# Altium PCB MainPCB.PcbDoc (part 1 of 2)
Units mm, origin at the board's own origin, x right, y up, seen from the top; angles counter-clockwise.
Board outline 105.16 x 70.61 mm, 2 copper layers (Top Layer, Bottom Layer); 130 components, 114 nets, 556 pads, 141 vias.
Unrouted connection lines stored in the file: 1.
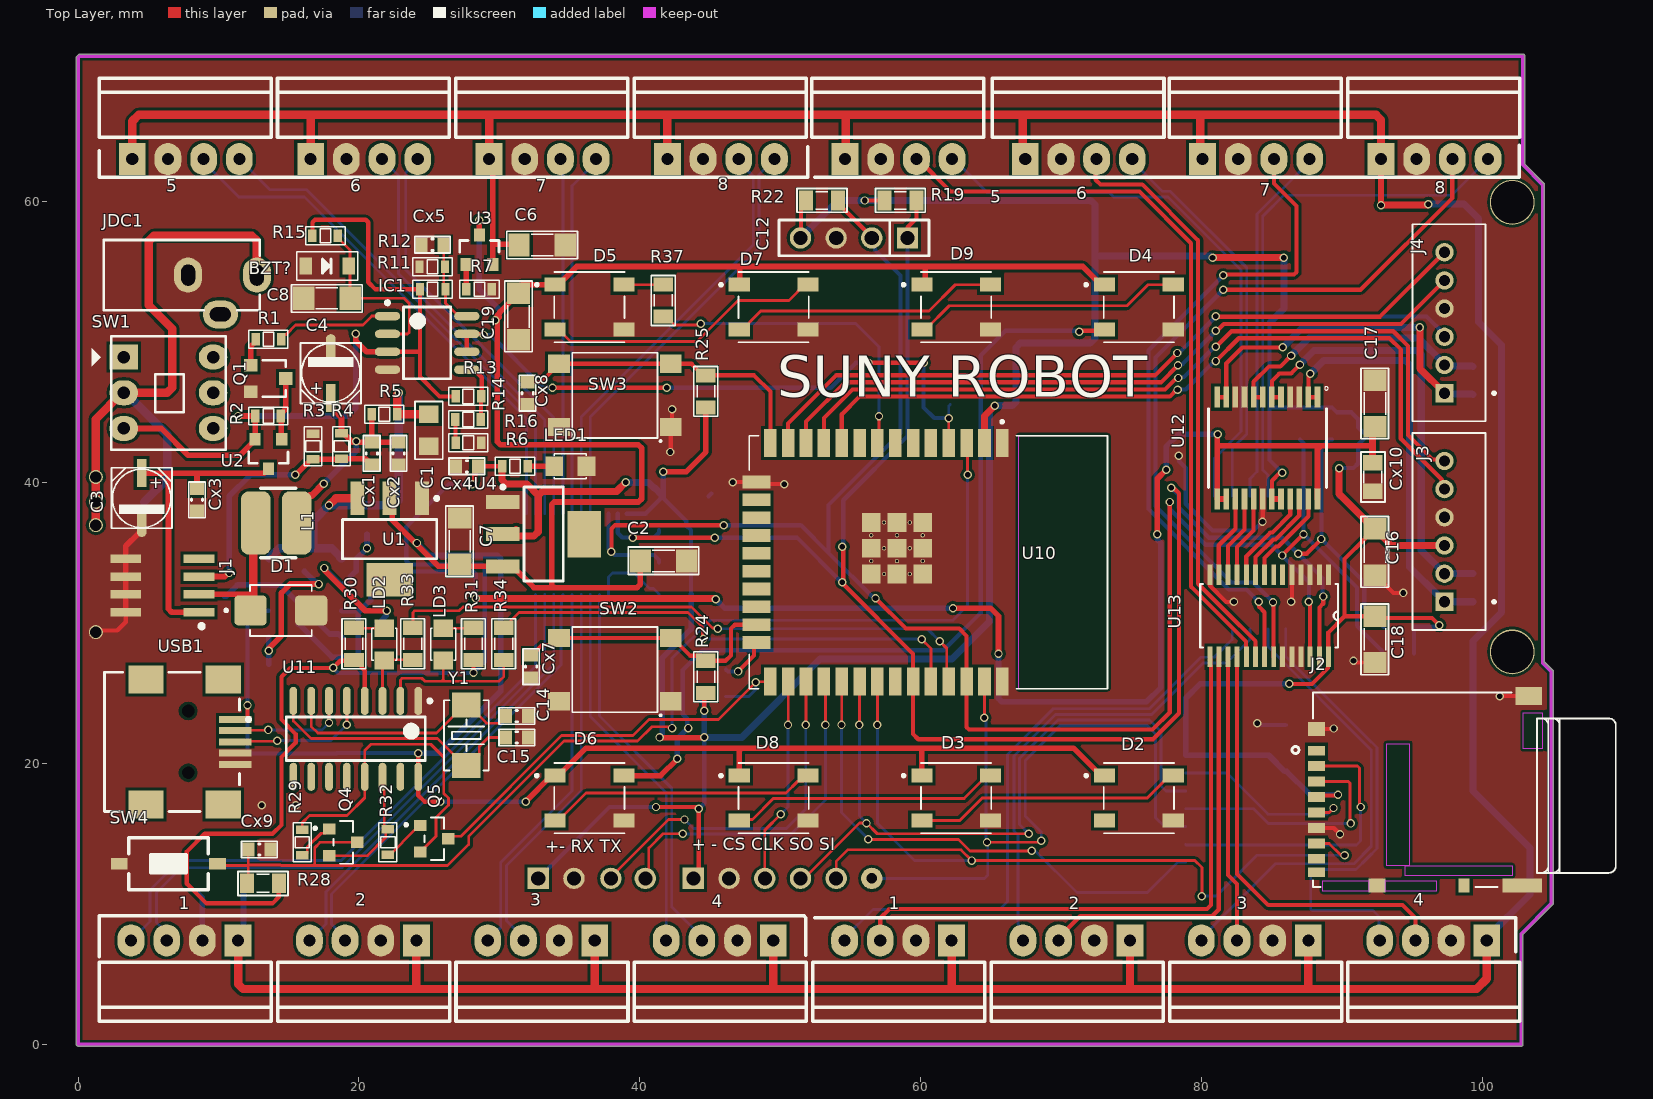
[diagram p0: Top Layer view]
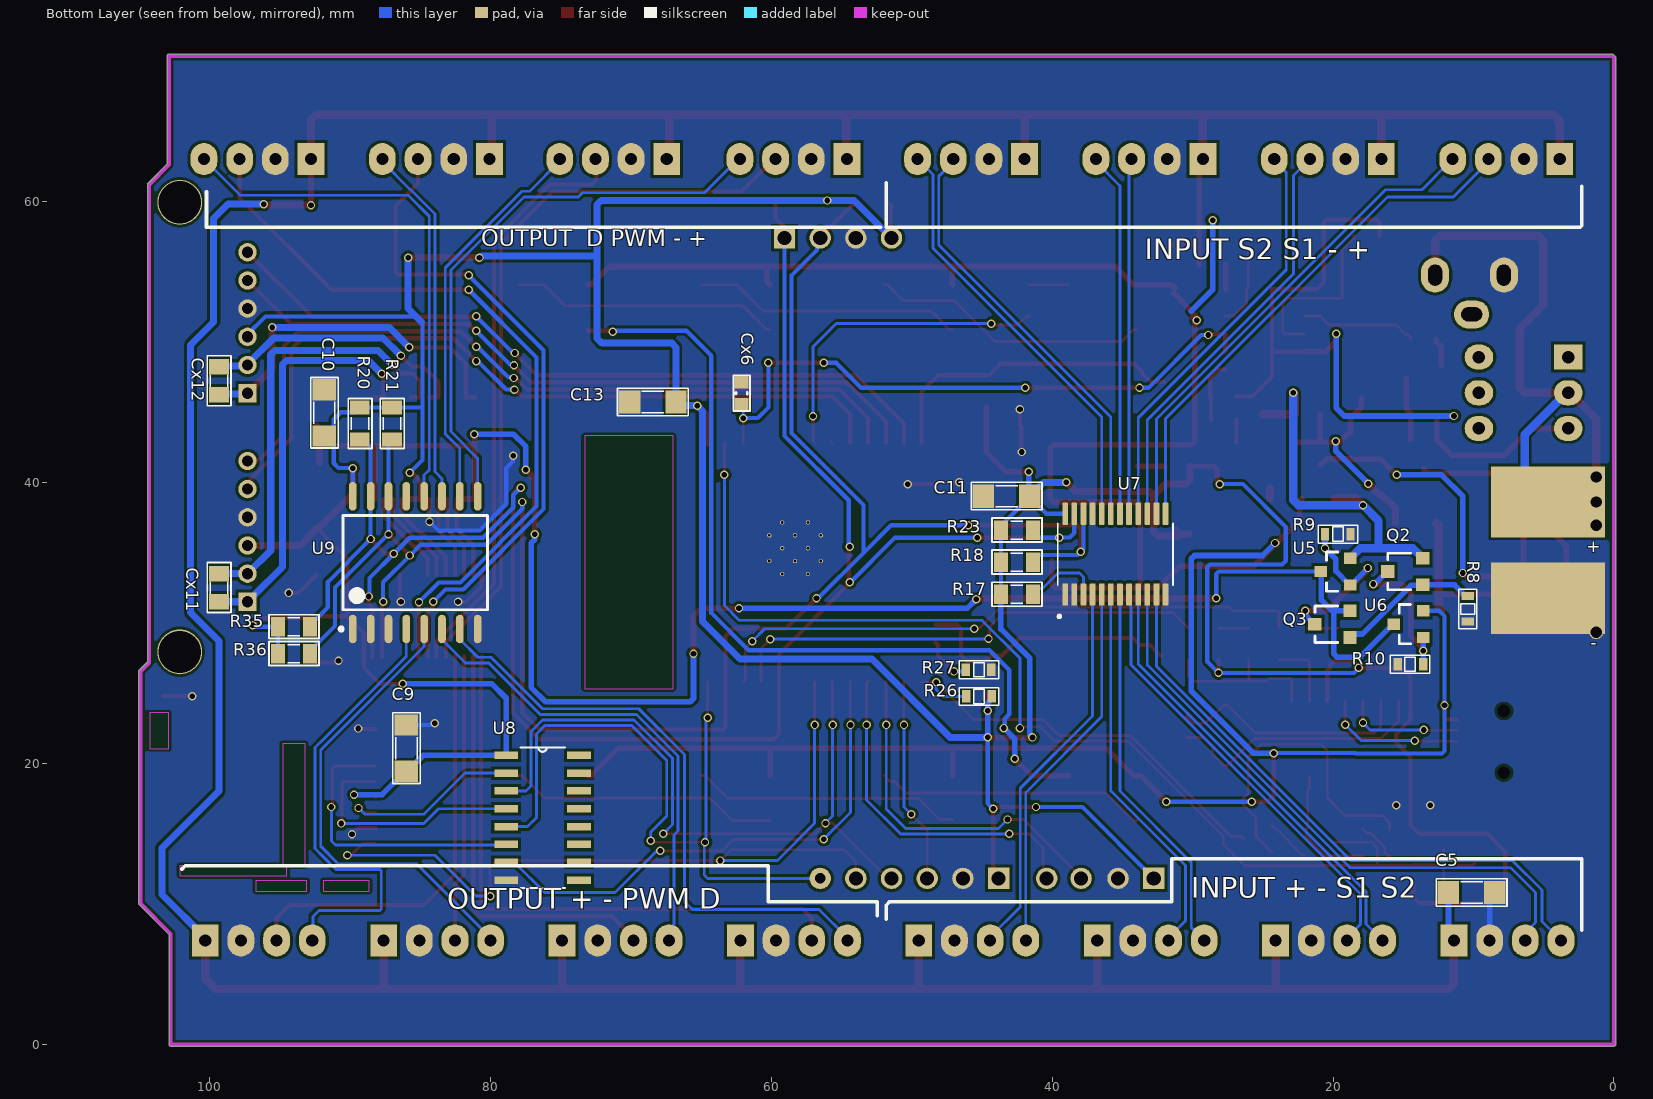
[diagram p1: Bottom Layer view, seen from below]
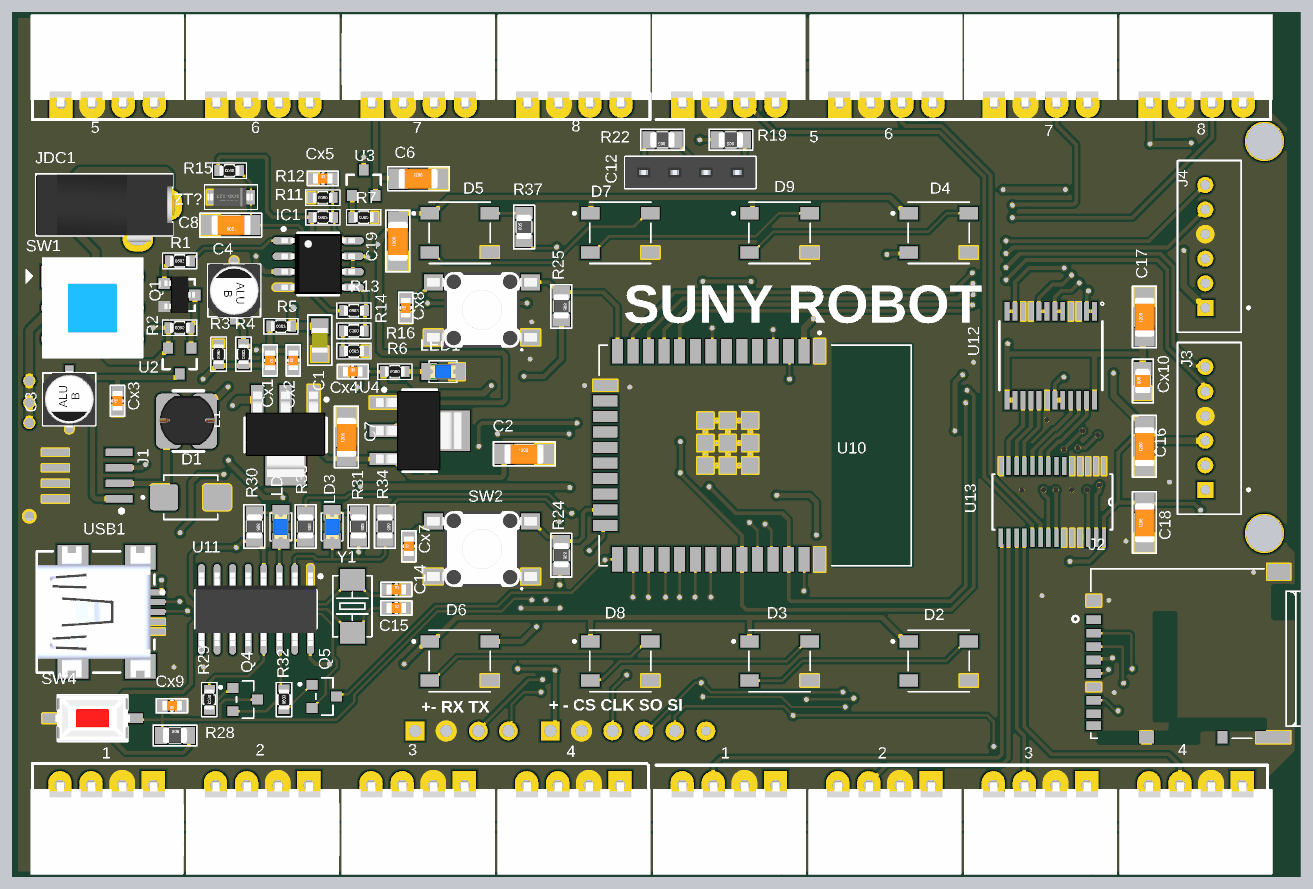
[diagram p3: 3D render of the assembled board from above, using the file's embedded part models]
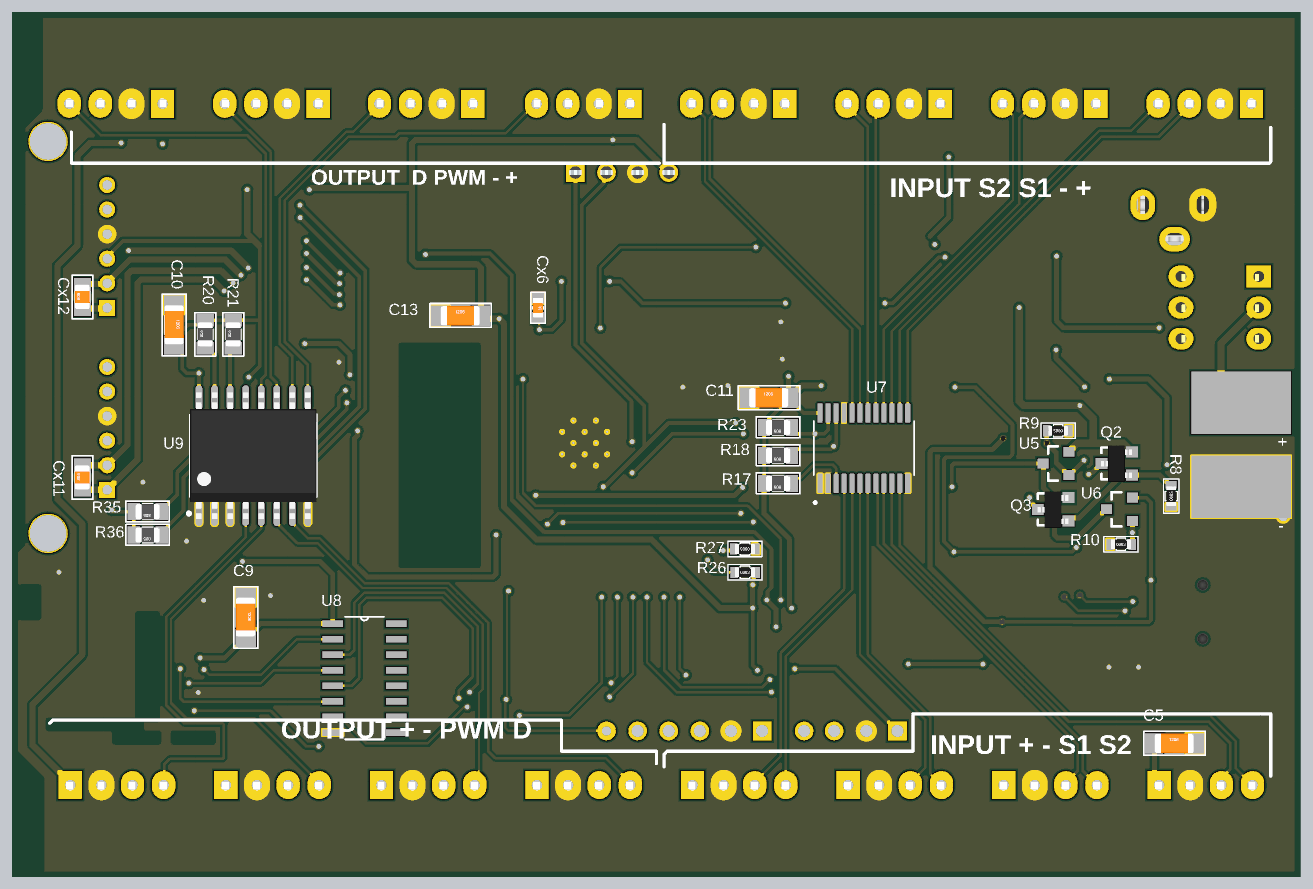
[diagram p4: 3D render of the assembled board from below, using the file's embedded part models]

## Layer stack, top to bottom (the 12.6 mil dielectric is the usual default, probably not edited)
Top Solder: solder mask 0.0102, Solder Resist, Dk 3.5
Top Layer: signal copper 0.0356
Dielectric 1: dielectric 0.32, FR-4, Dk 4.8
Bottom Layer: signal copper 0.0356
Bottom Solder: solder mask 0.0102, Solder Resist, Dk 3.5

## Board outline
0,-0.127 cw(c0,0) -0.127,0 -0.127,70.231 cw(c0,70.231) -0.09,70.322 -0.09,70.321 0.037,70.448 0.036,70.448 cw(c0.127,70.358) 0.127,70.485 102.87,70.485 cw(c102.87,70.358) 102.997,70.358 102.997,62.664 104.357,61.304 104.357,61.305 cw(c104.267,61.214) 104.394,61.214 104.394,27.231 104.992,26.633 104.992,26.634 cw(c104.902,26.543) 105.029,26.543 105.029,10.033 cw(c104.902,10.033) 104.992,9.942 104.992,9.943 102.87,7.821 102.87,0.127 cw(c102.743,0.127) 102.853,0.064 cw(c102.743,0) 102.87,0 cw(c102.743,0) 102.743,-0.127

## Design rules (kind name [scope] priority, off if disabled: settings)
Clearance [All] p1: gap=0.2 ignorepadtopadclearanceinfootprint=FALSE
PlaneClearance [All] p1: clearance=0.5
PlaneConnect [All] p1: planeconnectstyle=Relief reliefexpansion=0.5 reliefentries=4 reliefconductorwidth=0.5 reliefairgap=0.5
PolygonConnect [All] p1: connectstyle=Direct reliefconductorwidth=0.254 reliefentries=4 polygonreliefangle="90 Angle" airgapwidth=0.254
RoutingVias [All] p1: holewidth=0.4 width=0.6 viastyle="Through Hole" minholewidth=0.4 minwidth=0.6 maxholewidth=0.4 maxwidth=0.6
SolderMaskExpansion [All] p1: expansion=0.102 istentingtop=FALSE
Width Width_4 [InNetClass('Motor')] p1: maxlimit=0.5 minlimit=0.3 preferedwidth=0.4
Width Width_3 [InNetClass('LED')] p2: maxlimit=0.4 minlimit=0.2 preferedwidth=0.3
Width Width_2 [InNetClass('MCU')] p3: maxlimit=0.4 minlimit=0.2 preferedwidth=0.3
Width Width_1 [InNetClass('S_Power')] p4: maxlimit=0.4 minlimit=0.2 preferedwidth=0.3
Width [InNetClass('POWER')] p5: maxlimit=0.6 minlimit=0.4 preferedwidth=0.5
28 further rules are at their usual default settings.

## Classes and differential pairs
net class S_Power: +12 ADC_POWER EN_POWER_BAT GND NetBZT?_2 NetCx5_2 NetIC1_5 NetR14_2
net class POWER: +5 +5L +9 +12 +Vin +VM EN_POWER_BAT GND NetC3_1 NetC4_1 NetCx1_2 NetD1_C NetLED1_1 NetQ1_2 NetQ1_3 NetR7_2 TP TP1 TP2 VCC
net class Motor: +VM AO1 AO2 BO1 BO2 DIR_MA1 DIR_MA2 DIR_MB1 DIR_MB2 GND HAL_CHA_M1 HAL_CHA_M2 HAL_CHB_M1 HAL_CHB_M2 NetLabel438 NetLabel439 PWM_A PWM_B S1 S2 S3 S4 S5 S6 S7 S8 SCL SDA VCC
net class MCU: +5 ADC_POWER BT_Config BT_IN C_LED_WS2812 D+ D- DTR_CH340 EN GND GPIO_0 GPIO_2 HAL_CHA_M1 HAL_CHA_M2 HAL_CHB_M1 HAL_CHB_M2 MCU_RX MCU_TX NetLED2_1 NetLED3_1 NetQ4_1 NetQ5_1 NetR17_1 OP1 OP2 OP3 OP4 OP5 OP6 OP7 OP8 RST_CH340 S1 S2 S3 S4 S5 S6 S7 S8 SCL SCL_0 SCL_1 SCL_2 SCL_3 SCL_4 SCL_5 SCL_6 SCL_7 SD_CLK SD_CS SD_MOSI SDA SDA_0 SDA_1 SDA_2 SDA_3 SDA_4 SDA_5 SDA_6 SDA_7 SPI_CLK SPI_CS SPI_CS_SREEN SPI_MISO SPI_MOSI U2_RX U2_TX USB_RX USB_TX VCC XI XO
net class LED: +5 C_LED_WS2812 GND NetD5_4 OUT_1 OUT_2 OUT_3 OUT_4 OUT_5 OUT_6 OUT_7
component class Motor: C16 C17 C18 Cx10 Cx12 J3 J4 R35 U12 U13
component class MCU: 1 2 3 4 5 6 7 8 C9 C10 C11 C12 C13 C14 C15 Cx7 Cx8 Cx9 J2 LD2 LD3 Q4 Q5 R17 R18 R19 R20 R21 R22 R23 R24 R25 R26 R27 R28 R29 R31 R33 SW2 SW3 SW4 U7 U8 U9 U10 U11 USB1 Y1
component class LED: C19 D2 D3 D4 D5 D6 D7 D8 D9 R37
component class Power: + - BZT? C1 C2 C3 C4 C5 C6 C7 C8 Cx1 Cx2 Cx3 Cx4 Cx5 Cx6 D1 IC1 J1 JDC1 L1 LED1 Q1 Q2 Q3 R1 R2 R3 R4 R5 R6 R7 R8 R9 R10 R11 R12 R13 R14 R15 R16 SW1 U1 U2 U3 U4 U5 U6

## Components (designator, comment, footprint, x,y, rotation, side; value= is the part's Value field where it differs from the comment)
1 "Header 4" Header_4_ngang 62.193,7.392 r180 top locked (schematic designator P11)
1 "Header 4" Header_4_ngang 11.393,7.392 r180 top locked (schematic designator P1)
2 "Header 4" Header_4_ngang 74.893,7.392 r180 top locked (schematic designator P9)
2 "Header 4" Header_4_ngang 24.093,7.392 r180 top locked (schematic designator P2)
3 "Header 4" Header_4_ngang 87.593,7.392 r180 top locked (schematic designator P15)
3 "Header 4" Header_4_ngang 36.793,7.392 r180 top locked (schematic designator P3)
4 "Header 4" Header_4_ngang 100.293,7.392 r180 top locked (schematic designator P16)
4 "Header 4" Header_4_ngang 49.493,7.392 r180 top locked (schematic designator P4)
5 "Header 4" Header_4_ngang 54.61,63.018 r0 top (schematic designator P12)
5 "Header 4" Header_4_ngang 3.864,63.018 r0 top locked (schematic designator P5)
6 "Header 4" Header_4_ngang 67.437,63.018 r0 top (schematic designator P10)
6 "Header 4" Header_4_ngang 16.564,63.018 r0 top locked (schematic designator P6)
7 "Header 4" Header_4_ngang 80.064,63.018 r0 top (schematic designator P13)
7 "Header 4" Header_4_ngang 29.264,63.018 r0 top locked (schematic designator P7)
8 "Header 4" Header_4_ngang 92.764,63.018 r0 top (schematic designator P14)
8 "Header 4" Header_4_ngang 41.964,63.018 r0 top (schematic designator P8)
+ "Ac" BAT_BK-6223 4.699,38.608 r180 top (schematic designator BT1)
- "Pos" BAT_BK-6223 4.699,31.75 r180 top (schematic designator BT2)
BZT? "Diode SMD" DIO-SMD-123 17.743,55.398 r180 top value=1N5007
C1 "104" C-0805 24.982,43.714 r90 top value=103
C2 "22uF 16V" CN-SMD-1206 41.656,34.417 r0 top value=103
C3 "47uF/16V" CAP-ALU-SMD-5.5x5.5 4.535,38.888 r270 top
C4 "47uF/16V" CAP-ALU-SMD-5.5x5.5 17.997,47.778 r90 top
C5 "22uF 16V" CN-SMD-1206 10.16,10.795 r180 bottom value=103
C6 "22uF 16V" CN-SMD-1206 33.02,56.896 r0 top value=103
C7 "22uF 16V" CN-SMD-1206 27.178,35.789 r90 top value=103
C8 "10uF 16V" CN-SMD-1206 17.743,53.112 r180 top value=103
C9 "22uF 6.3" CN-SMD-1206 85.979,21.107 r270 bottom value=103
C10 "22uF 6.3" CN-SMD-1206 91.821,44.983 r270 bottom value=103
C11 "22uF 6.3" CN-SMD-1206 43.27,39.015 r180 bottom value=103
C12 "Header4" JP4-C1T 59.055,57.404 r180 top
C13 "22uF 6.3V" CN-SMD-1206 68.453,45.72 r180 bottom value=103
C14 "22pF" CN-SMD-0603 31.242,23.368 r0 top value=103
C15 "22pF" CN-SMD-0603 31.242,21.844 r0 top value=103
C16 "22uF 6.3V" CN-SMD-1206 92.329,35.027 r90 top value=103
C17 "22uF 16V" CN-SMD-1206 92.329,45.593 r90 top value=103
C18 "22uF 6.3V" CN-SMD-1206 92.329,28.804 r90 top value=103
C19 "22uF 6.3" CN-SMD-1206 31.369,51.791 r90 top value=103
Cx1 "2.2nF" CN-SMD-0603 20.918,42.063 r270 top value=33pF
Cx2 "104" CN-SMD-0603 22.823,42.063 r90 top value=33pF
Cx3 "104" CN-SMD-0603 8.472,38.761 r90 top value=33pF
Cx4 "104" CN-SMD-0603 27.686,41.148 r0 top value=33pF
Cx5 "100nF" CN-SMD-0603 25.236,56.922 r0 top value=33pF
Cx6 "104" CN-SMD-0603 62.103,46.355 r270 bottom value=33pF
Cx7 "104" CN-SMD-0603 32.258,26.886 r90 top value=33pF
Cx8 "104" CN-SMD-0603 32.004,46.355 r90 top value=33pF
Cx9 "104" CN-SMD-0603 12.917,13.869 r180 top value=33pF
Cx10 "104" CN-SMD-0805 92.177,40.386 r90 top value=33pF
Cx11 "104" CN-SMD-0805 99.314,32.512 r90 bottom value=33pF
Cx12 "104" CN-SMD-0805 99.314,47.244 r90 bottom value=33pF
D1 "SS34" DIOM5336X265N 14.441,30.887 r0 top
D2 "WS2812 5050" LED_1655 75.524,17.526 r0 top
D3 "WS2812 5050" LED_1655 62.524,17.526 r0 top
D4 "WS2812 5050" LED_1655 75.524,52.476 r0 top
D5 "WS2812 5050" LED_1655 36.412,52.476 r0 top
D6 "WS2812 5050" LED_1655 36.412,17.526 r0 top
D7 "WS2812 5050" LED_1655 49.524,52.476 r0 top
D8 "WS2812 5050" LED_1655 49.524,17.526 r0 top
D9 "WS2812 5050" LED_1655 62.524,52.476 r0 top
IC1 "LM358" SO8 24.855,49.937 r0 top
J1 "XL1509_5V" SO08 5.999,32.665 r90 top
J2 "DM3AT-SF-PEJM5" HRS_DM3AT-SF-PEJM5 88.179,17.703 r90 top
J3 "1735446-6" TE_1735446-6 97.282,36.513 r270 top
J4 "1735446-6" TE_1735446-6 97.282,51.371 r270 top
JDC1 "Jac DC" DC3 12.737,54.763 r0 top
L1 "68uH 2A" "SMD Inductors CD54" 12.663,37.11 r90 top value="150 mH"
LD2 "LED" LED-0805-Blue 21.807,29.617 r270 top value="LED 3 - 5 ly 2 Colour" (schematic designator LED2)
LD3 "LED" LED-0805-Blue 25.998,29.617 r270 top value="LED 3 - 5 ly 2 Colour" (schematic designator LED3)
LED1 "LED" LED-0805-Blue 33.909,41.148 r0 top value="LED 3 - 5 ly 2 Colour"
Q1 "2SC1815" SOT23-321 13.537,47.397 r270 top value=C1815
Q2 "2SA1015" SOT23-321 14.859,33.655 r90 bottom value=A1015
Q3 "2SA1015" SOT23-321 20.046,29.906 r90 bottom value=A1015
Q4 "MMSS8050-H-TP" TRANS_MMSS8050-H-TP 18.886,14.377 r0 top
Q5 "MSS8050-H-TP" TRANS_MMSS8050-H-TP 25.363,14.631 r0 top
R1 "330" RES-SMD-0603 13.552,50.191 r0 top value=2k
R2 "330" RES-SMD-0603 13.552,44.73 r180 top value=10k
R3 "240R" RES-SMD-0603 16.727,42.571 r270 top
R4 "1.5K" RES-SMD-0603 18.759,42.571 r90 top
R5 "0R" RES-SMD-0603 21.807,44.857 r0 top
R6 "220R" RES-SMD-0603 31.115,41.148 r180 top
R7 "10k" RES-SMD-0603 28.575,53.747 r180 top
R8 "10k" RES-SMD-0603 10.414,30.988 r90 bottom
R9 "10k" RES-SMD-0603 19.647,36.322 r0 bottom
R10 "10k" RES-SMD-0603 14.516,27.051 r180 bottom
R11 "10k" RES-SMD-0603 25.236,53.747 r0 top
R12 "10k" RES-SMD-0603 25.236,55.353 r180 top
R13 "100k" RES-SMD-0603 27.776,46.127 r0 top
R14 "33k" RES-SMD-0603 27.776,44.476 r180 top
R15 "1k" RES-SMD-0603 17.616,57.557 r180 top
R16 "2k" RES-SMD-0603 27.776,42.825 r0 top
R17 "4k7" RES-SMD-0805 42.508,32.03 r0 bottom
R18 "4k7" RES-SMD-0805 42.508,34.316 r0 bottom
R19 "4k7" RES-SMD-0805 58.547,60.071 r180 top
R20 "4k7" RES-SMD-0805 89.281,44.196 r90 bottom
R21 "4k7" RES-SMD-0805 86.995,44.196 r90 bottom
R22 "4k7" RES-SMD-0805 52.959,60.071 r180 top
R23 "4k7" RES-SMD-0805 42.508,36.602 r0 bottom
R24 "10k" RES-SMD-0805 44.704,26.162 r270 top
R25 "10k" RES-SMD-0805 44.704,46.482 r270 top
R26 "10k" RES-SMD-0603 45.212,24.765 r180 bottom
R27 "10k" RES-SMD-0603 45.212,26.67 r0 bottom
R28 "10k" RES-SMD-0805 13.171,11.456 r0 top
R29 "10k" RES-SMD-0603 15.965,14.377 r270 top
R30 "1k" RES-SMD-0805 19.648,28.512 r270 top
R31 "1k" RES-SMD-0805 28.157,28.512 r270 top
R32 "10k" RES-SMD-0603 22.061,14.377 r90 top
R33 "470" RES-SMD-0805 23.839,28.512 r270 top
R34 "470" RES-SMD-0805 30.316,28.512 r270 top
R35 "4k7" RES-SMD-0805 93.98,29.718 r0 bottom
R36 "4k7" RES-SMD-0805 93.98,27.813 r0 bottom
R37 "470" RES-SMD-0805 41.656,52.959 r90 top
SW1 "Switch 3x2" SW3-DIP 6.567,46.381 r0 top value="Switch 4x2"
SW2 "SW" SW2-SMD 38.227,26.67 r180 top value="Button chip 4 pin"
SW3 "SW" SW2-SMD 38.227,46.192 r180 top value="Button chip 4 pin"
SW4 "SW" SW1-SMD 6.44,12.853 r180 top value="SW chip 2 pin"
U1 "LM1117-5V" SOT223 22.188,35.967 r180 top
U2 "AO3401" SOT23-3 13.552,42.063 r180 top
U3 "AO3401" SOT23-3 28.575,56.515 r0 top
U4 "LM1117-3.3V" SOT223 33.147,36.322 r270 top
U5 "AO3401" SOT23-3 19.771,33.655 r90 bottom
U6 "AO3401" SOT23-3 14.584,29.911 r90 bottom
U7 "TCA9548APWR" SOP65P640X120-24N 35.497,34.9 r90 bottom
U8 "74HC4050D,653" SOIC127P600X175-16N 76.276,16.129 r180 bottom
U9 "PCF8574" SO16L 85.344,34.29 r90 bottom
U10 "ESP32-WROOM-32" MODULE_ESP32-WROOM-32 60.542,34.316 r270 top locked
U11 "CH340G" SO16 19.775,21.743 r270 top
U12 "TB6612FNG,C,8,EL" SOP65P760X160-24N 84.672,42.444 r270 top
U13 "PCA9685PW,112" SOP65P640X110-28N 84.799,30.506 r270 top
USB1 "USB2.0" "USB mini" 2.587,21.53 r180 top
Y1 "12M-5032" X2-SMD-5.0X3.2X1.3MM 27.649,21.997 r90 top

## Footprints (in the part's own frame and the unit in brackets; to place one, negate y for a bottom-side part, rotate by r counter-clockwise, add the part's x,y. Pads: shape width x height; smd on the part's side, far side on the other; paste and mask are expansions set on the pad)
BAT_BK-6223 [mm]
  rect 8.13x5.08 smd far side: 1(0,0)
C-0805 [mil] "Compoment SMD 80x50mil"
  rect 50x55 smd: 1(-45,0) 2(45,0)
  silkscreen extent -81,-39 81,39, body extent -40,-25 40,25, height 24
CAP-ALU-SMD-5.5x5.5 [mm]
  rect 2x0.7 smd: 1(-1.778,0)
  oval 2x0.7 smd: 2(1.778,0)
  silkscreen extent -2.15,-2.15 2.15,2.15, body extent -2.3,-2.15 2.3,2.15, height 5.4
CN-SMD-0603 [mm]
  rect 0.9x1 smd: 1(-0.8,0) 2(0.8,0)
  silkscreen extent -1.27,-0.58 1.27,0.58, body extent -0.8,-0.4 0.8,0.4, height 0.3
CN-SMD-0805 [mm]
  rect 1.1x1.397 smd: 1(-1,0) 2(1,0)
  silkscreen extent -1.78,-0.86 1.78,0.84, body extent -1,-0.62 1,0.63, height 0.8
CN-SMD-1206 [mil]
  rect 60x65 smd: 1(-64,0) 2(66,0)
  silkscreen extent -98,-38 100,39, body extent -63,-31 63,32, height 40
DC3 [mm] "WR-DC_DC Power Jack_Right Angled_THT Center Pin ?1.0_Plug ID ?1.05_Plug OD ?3.5"
  oval 2x2.5 hole 1 slot 1.5 at 90 deg: 1(0,0) 2(-4.9,0)
  oval 2.5x2 hole 1 slot 1.5 at 0 deg: 3(-2.6,-2.8)
  silkscreen extent -10.9,-2.5 0.2,2.5, body extent -10.9,-3 0.4,2.5, height 7.81
DIO-SMD-123 [mm]
  rect 0.9x1.2 smd: 1(1.524,0) 2(-1.524,0)
  silkscreen extent -2.16,-1.02 2.16,1.02, body extent -1.76,-0.8 1.94,0.8, height 1.25
DIOM5336X265N [mm]
  rrect25% 2.29x2.12 smd: A(2.16,0) C(-2.16,0)
  silkscreen extent -4,-1.81 2.2,1.81
Header_4_ngang [mil]
  rect 75x90 hole 34.02: 1(0,0)
  oval 75x90 hole 34.02: 2(100,0) 3(200,0) 4(300,0)
  silkscreen extent -93,61 389,226, body extent -98,-12 394,288, height 229
HRS_DM3AT-SF-PEJM5 [mm]
  rect 0.7x1.2 smd: 1(3.2,0) 2(2.1,0) 3(1,0) 4(-0.1,0) 5(-1.2,0) 6(-2.3,0) 7(-3.4,0) 8(-4.5,0) SWB(-5.45,0)
  rect 1x1.2 smd: P1(-6.4,-4.3) P4(4.75,0)
  rect 1x2.8 smd: P2(-6.4,-14.65)
  rect 1.3x1.9 smd: P3(7.1,-15.1)
  rect 1x0.8 smd: SWA(-6.4,-10.5)
  Keep-Out Layer region: 5.9,-16.057 3.351,-16.057 3.351,-14.7 5.9,-14.7
  Keep-Out Layer region: 3.7,-6.604 -5.003,-6.604 -5.003,-5 3.7,-5
  Keep-Out Layer region: -5,-13.915 -5.706,-13.915 -5.706,-6.3 -5,-6.3
  Keep-Out Layer region: -6.05,-8.505 -6.804,-8.505 -6.804,-4.9 -6.05,-4.9
  Keep-Out Layer region: -6.05,-3.707 -6.813,-3.707 -6.813,-0.45 -6.05,-0.45
  silkscreen extent -6.5,-21.3 7.35,1.75
JP4-C1T [mm] "4 row, straight, gold plating"
  rect 1.52x1.52 hole 1.02: 1(0,0)
  round 1.52 hole 1.02: 2(2.54,0) 3(5.08,0) 4(7.62,0)
  silkscreen extent -1.52,-1.27 9.14,1.27, body extent -1.52,-1.25 9.14,1.25, height 8.51
LED-0805-Blue [mil]
  rect 50x55 smd: 1(0,0) 2(90,0)
  silkscreen extent 0,-35 90,35, body extent 5,-25 85,25, height 43
LED_1655 [mm]
  rect 1.5x1 smd: 1(-2.45,1.6) 2(-2.45,-1.6) 3(2.45,-1.6) 4(2.45,1.6)
  silkscreen extent -3.85,-2.5 2.5,2.5
MODULE_ESP32-WROOM-32 [mm]
  rect 2x0.9 smd: 1(-8.5,5.26) 2(-8.5,3.99) 3(-8.5,2.72) 4(-8.5,1.45) 5(-8.5,0.18) 6(-8.5,-1.09) 7(-8.5,-2.36) 8(-8.5,-3.63) 9(-8.5,-4.9) 10(-8.5,-6.17) 11(-8.5,-7.44) 12(-8.5,-8.71) 13(-8.5,-9.98) 14(-8.5,-11.25) 25(8.5,-11.25) 26(8.5,-9.98) 27(8.5,-8.71) 28(8.5,-7.44) 29(8.5,-6.17) 30(8.5,-4.9) 31(8.5,-3.63) 32(8.5,-2.36) 33(8.5,-1.09) 34(8.5,0.18) 35(8.5,1.45) 36(8.5,2.72) 37(8.5,3.99) 38(8.5,5.26)
  rect 0.9x2 smd: 15(-5.715,-12.25) 16(-4.445,-12.25) 17(-3.175,-12.25) 18(-1.905,-12.25) 19(-0.635,-12.25) 20(0.635,-12.25) 21(1.905,-12.25) 22(3.175,-12.25) 23(4.445,-12.25) 24(5.715,-12.25)
  rect 1.33x1.33 smd: 39_1(-2.835,-0.405) 39_2(-1,-0.405) 39_3(0.835,-0.405) 39_4(-2.835,-2.24) 39_5(-1,-2.24) 39_6(0.835,-2.24) 39_7(-2.835,-4.075) 39_8(-1,-4.075) 39_9(0.835,-4.075)
  round 0.3 hole 0.2: 39_10(-1.917,-0.405) 39_11(-0.082,-0.405) 39_12(-2.835,-1.322) 39_13(-1,-1.322) 39_14(0.835,-1.322) 39_15(-1.917,-2.24) 39_16(-0.082,-2.24) 39_17(-2.835,-3.157) 39_18(-1,-3.157) 39_19(0.835,-3.157) 39_20(-1.917,-4.075) 39_21(-0.082,-4.075)
  Keep-Out Layer region: 9,6.45 -9,6.45 -9,12.75 9,12.75
  Keep-Out Layer region: 9,6.45 -9,6.45 -9,12.75 9,12.75
  silkscreen extent -10.1,-12.75 9,12.75
RES-SMD-0603 [mm]
  rect 0.6x0.9 smd: 1(-0.889,0) 2(0.927,0)
  silkscreen extent -1.4,-0.64 1.4,0.64, body extent -0.8,-0.4 0.8,0.4, height 0.43
RES-SMD-0805 [mil]
  rect 39.37x55 smd: 1(-45,0) 2(45,0)
  silkscreen extent -70,-34 70,33, body extent -39,-25 39,25, height 31
"SMD Inductors CD54" [mm]
  rrect50% 4.5x2.1 smd: 1(0,0) 2(0,-2.9)
  silkscreen extent -2.47,-2.85 2.47,-0.35, body extent -1.95,-3.75 2.05,0.75, height 3.25
SO8 [mm] "SOIC, 8-Leads, Body 4.9x3.9mm, Pitch 1.27mm, IPC High Density"
  oval 1.8x0.6 smd: 1(-2.825,1.905) 2(-2.825,0.635) 3(-2.825,-0.635) 4(-2.825,-1.905) 5(2.825,-1.905) 6(2.825,-0.635) 7(2.825,0.635) 8(2.825,1.905)
  silkscreen extent -2.95,-2.55 1.68,2.98, body extent -2.99,-2.45 3,2.45, height 1.6
SO08 [mm]
  rect 0.6x2.2 smd: 1(-1.905,-2.6) 2(-0.635,-2.6) 3(0.635,-2.6) 4(1.905,-2.6) 5(1.905,2.6) 6(0.635,2.6) 7(-0.635,2.6) 8(-1.905,2.6)
  silkscreen extent -3.04,-2.94 -2.76,-2.66
SO16 [mm] "SOIC, 16-Leads, Body 9.90x3.91mm, Pitch 1.27mm, IPC Medium Density"
  oval 2x0.55 smd: 1(-2.7,4.445) 2(-2.7,3.175) 3(-2.7,1.905) 4(-2.7,0.635) 5(-2.7,-0.635) 6(-2.7,-1.905) 7(-2.7,-3.175) 8(-2.7,-4.445) 9(2.7,-4.445) 10(2.7,-3.175) 11(2.7,-1.905) 12(2.7,-0.635) 13(2.7,0.635) 14(2.7,1.905) 15(2.7,3.175) 16(2.7,4.445)
  silkscreen extent -2.82,-4.95 1.55,5.4, body extent -3,-4.95 3,4.95, height 1.4
SO16L [mm] "SOIC, 16-Leads, Body 10.30x7.50mm, Pitch 1.27mm, IPC Medium Density"
  oval 2.032x0.55 smd: 1(-4.725,4.445) 2(-4.725,3.175) 3(-4.725,1.905) 4(-4.725,0.635) 5(-4.725,-0.635) 6(-4.725,-1.905) 7(-4.725,-3.175) 8(-4.725,-4.445) 9(4.725,-4.445) 10(4.725,-3.175) 11(4.725,-1.905) 12(4.725,-0.635) 13(4.725,0.635) 14(4.725,1.905) 15(4.725,3.175) 16(4.725,4.445)
  silkscreen extent -4.85,-5.15 3.35,5.4, body extent -5.15,-5.17 5.16,5.16, height 2.48
SOIC127P600X175-16N [mil]
  rect 67x21 smd: 1(-102,175) 2(-102,125) 3(-102,75) 4(-102,25) 5(-102,-25) 6(-102,-75) 7(-102,-125) 8(-102,-175) 9(102,-175) 10(102,-125) 11(102,-75) 12(102,-25) 13(102,25) 14(102,75) 15(102,125) 16(102,175)
  silkscreen extent -62,-197 62,197
SOP65P640X110-28N [mil]
  rect 58x14 smd: 1(-115,166) 2(-115,141) 3(-115,115) 4(-115,90) 5(-115,64) 6(-115,38) 7(-115,13) 8(-115,-13) 9(-115,-38) 10(-115,-64) 11(-115,-90) 12(-115,-115) 13(-115,-141) 14(-115,-166) 15(115,-166) 16(115,-141) 17(115,-115) 18(115,-90) 19(115,-64) 20(115,-38) 21(115,-13) 22(115,13) 23(115,38) 24(115,64) 25(115,90) 26(115,115) 27(115,141) 28(115,166)
  silkscreen extent -89,-193 89,193
SOP65P640X120-24N [mm]
  rrect25% 1.57x0.41 smd: 1(-2.87,3.575) 2(-2.87,2.925) 3(-2.87,2.275) 4(-2.87,1.625) 5(-2.87,0.975) 6(-2.87,0.325) 7(-2.87,-0.325) 8(-2.87,-0.975) 9(-2.87,-1.625) 10(-2.87,-2.275) 11(-2.87,-2.925) 12(-2.87,-3.575) 13(2.87,-3.575) 14(2.87,-2.925) 15(2.87,-2.275) 16(2.87,-1.625) 17(2.87,-0.975) 18(2.87,-0.325) 19(2.87,0.325) 20(2.87,0.975) 21(2.87,1.625) 22(2.87,2.275) 23(2.87,2.925) 24(2.87,3.575)
  silkscreen extent -4.54,-4.1 2.2,4.1
SOP65P760X160-24N [mm]
  rect 1.5x0.4 smd: 1(-3.625,3.575) 2(-3.625,2.925) 3(-3.625,2.275) 4(-3.625,1.625) 5(-3.625,0.975) 6(-3.625,0.325) 7(-3.625,-0.325) 8(-3.625,-0.975) 9(-3.625,-1.625) 10(-3.625,-2.275) 11(-3.625,-2.925) 12(-3.625,-3.575) 13(3.625,-3.575) 14(3.625,-2.925) 15(3.625,-2.275) 16(3.625,-1.625) 17(3.625,-0.975) 18(3.625,-0.325) 19(3.625,0.325) 20(3.625,0.975) 21(3.625,1.625) 22(3.625,2.275) 23(3.625,2.925) 24(3.625,3.575)
  silkscreen extent -4.38,-4.2 2.8,4.33
SOT23-3 [mm]
  rect 0.8x0.9 smd: 1(-0.95,-1) 2(0.95,-1) 3(0,1.1)
  silkscreen extent -1.4,-0.1 1.4,0.7
SOT23-321 [mm]
  rect 0.9x0.95 smd mask+0: 1(0.95,-1.25)
  rect 0.9x0.95 smd: 2(0,1.25) 3(-0.95,-1.25)
  silkscreen extent -1.3,-0.38 1.3,1.25, body extent -1.52,-1.23 1.48,1.27, height 1.06
SOT223 [mm]
  rect 1x2.4 smd: 1(-2.3,-2.9) 2(0,-2.9) 3(2.3,-2.9)
  rect 3.3x2.4 smd: 4(0,2.9)
  silkscreen extent -3.48,-3.02 3.35,1.4, body extent -3.25,-3.56 3.25,3.4, height 1.68
SW1-SMD [mm]
  rect 1.2x0.8 smd: 1(-3.5,0) 2(3.5,0)
  silkscreen extent -2.82,-1.85 2.82,1.85, body extent -3.05,-1.85 3.05,1.85, height 2.5
SW2-SMD [mm] "6*6mm vertical type, SMD, height 5.0mm, black actuator, 160gf, T&R"
  rect 1.55x1.3 smd: 1(-3.975,2.25) 2(-3.975,-2.25) 3(3.975,-2.25) 4(3.975,2.25)
  silkscreen extent -3.29,-3.04 3.04,3.29, body extent -4.5,-3.1 4.5,3.1, height 4.99
SW3-DIP [mil] "SW DTDP - 6Pin 260x300x300 mil"
  rect 80x70 hole 35: 1(-130,100)
  oval 80x70 hole 35: 2(-130,0) 3(-130,-100) 4(120,-100) 5(120,0) 6(120,100)
  silkscreen extent -220,-160 155,158, body extent -163,-159 151,155, height 532
TE_1735446-6 [mm]
  rect 1.308x1.308 hole 0.8: 1(5.016,0)
  round 1.308 hole 0.8: 2(3.01,0) 3(1.003,0) 4(-1.003,0) 5(-3.01,0) 6(-5.016,0)
  silkscreen extent -7.02,-2.27 7.02,3.63
TRANS_MMSS8050-H-TP [mm]
  rect 0.9x0.8 smd: 1(-1,0.95) 2(-1,-0.95) 3(1,0)
  silkscreen extent -2.1,-1.52 0.7,1.52
"USB mini" [mm] "Connector; USB2.0, Type B, SM; 5 Position; Right Angle"
  rect 2.3x0.5 smd: 1(-8.6,-1.6) 2(-8.6,-0.8) 3(-8.6,0) 4(-8.6,0.8) 5(-8.6,1.6)
  rect 2.5x2 smd: 6(-7.75,4.45) 7(-2.25,4.45) 8(-7.75,-4.45) 9(-2.25,-4.45)
  round 0.6 hole 0.9 unplated: MH1(-5.25,2.2) MH2(-5.25,-2.2)
  silkscreen extent -9.68,-4.95 0.7,4.95, body extent -8.56,-5.35 0.64,5.35, height 3.97
X2-SMD-5.0X3.2X1.3MM [mil]
  rect 70x80 smd: 1(-85,0) 2(85,0)
  silkscreen extent -98,-63 98,63

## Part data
1 1 2 2 3 3 4 4 5 5 6 6 7 7 8 8: "Header, 4-Pin"
+ -: library part BK-6223, "AAAA Battery Contact", Package="Non-Standard MPD"
BZT?: "Default Diode"
C1 C14 C15: library part C, "Cap SMD"
C2 C5 C6 C7 C8 C9 C10 C11 C13 C16 C17 C18 C19: library part C, "Cap SMD 1206 >5V"
C3 C4: library part CN-ALU-SMD, "Polarized Capacitor (Axial)"
C12: "Header IDC, 4 x 1 Pin Vertical 2.54mm Pitch (Non-Boxed, Male)", Manufacturer="W¨¹rth Elektronik eiSos GmbH", partNo=613002143121
Cx1 Cx2 Cx3 Cx4 Cx5 Cx6 Cx7 Cx8 Cx9 Cx10 Cx11 Cx12: library part CN
D1: library part SS24, "1", Package="DO-214AA-214 TE Connectivity / Alcoswitch"
D2 D3 D4 D5 D6 D7 D8 D9: library part 1655, "Addressable Lighting Neopixel 10 LED Discrete Serial _Shift Register_ Red, Green, Blue _RGB_ 5.00mm L x 5.00mm W", Package="TSOP-38238 Adafruit Industries"
IC1: "Low-Power Dual Operational Amplifier"
J1: library part AP1509-50SG-13, "Buck Switching Regulator IC Positive Fixed 5V 1 Output 2A 8-SOIC (0.154, 3.90mm Width)", Package="SOP-8 Diodes Inc."
J2: "10ï¼ˆ8 + 2ï¼‰ä½ç½®å¡è¿žæŽ¥å™¨å®‰å…¨æ•°å­—-microSDâ„¢è¡¨é¢å®‰è£…ï¼Œç›´è§’é‡‘", Package=None
J3 J4: "2MM PITCH HPI POST HEADER, VERTICAL, 6P", Package=None
JDC1: library part DCIN, "Jac DC input"
L1: library part L-DIP-1, "Inductor"
LD2 LD3 LED1: library part "LED SMD"
Q1: "NPN 600mW, ECB"
Q2 Q3: "PNP 600mW, ECB"
Q4: "Bipolar _BJT_ Transistor NPN 25V 1.5A 100MHz 625mW Surface Mount SOT-23", Package="SOT-23 Micro Commercial"
Q5: library part MMSS8050-H-TP, "Bipolar _BJT_ Transistor NPN 25V 1.5A 100MHz 625mW Surface Mount SOT-23", Package="SOT-23 Micro Commercial"
R1 R2: library part "RESISTOR SMD", "330R"
R3 R4 R5 R6 R7 R8 R9 R10 R11 R12 R13 R14 R15 R16 R17 R18 R19 R20 R21 R22 R23 R24 R25 R26 R27 R28 R29 R30 R31 R32 R33 R34 R35 R36 R37: library part Res-SMD, "Resistor", Manufacturer="Generic Components"
SW1: library part SW3x2
SW2 SW3: library part SW4, "Switch button 4 pin"
SW4: library part SW2, "Switch button 2 pin"
U1 U4: library part LM1117, "800mA Low-Dropout Linear Regulator"
U2 U3 U5 U6: "P-Channel 30V 4A (Ta) 1.4W (Ta) Surface Mount SOT-23-3L", Package="SOT-23-3 Alpha &amp; Omega Semiconductor"
U7: "Low-Voltage 8-Channel I2C Switch With Reset", Package="TSSOP-24 Texas Instruments"
U8: "Buffer, Non-Inverting 6 Element 1 Bit per Element Push-Pull Output 16-SO", Package="SO-16 Nexperia"
U9: "I2C PORT EXPANDER", Frequency - Clock=100KHz, Manufacturer="NXP Semiconductors", Manufacturer Part Number=PCF8574T/3,512, Operating Temperature="-40°C ~ 85°C", Package / Case="16-SOIC (7.5mm Width)", Supplier Part Number=568-1076-5-ND, Voltage - Supply="2.5 V ~ 6 V"
U10: "Bluetooth, WiFi Transceiver Module 2.4GHz ~ 2.5GHz Surface Mount", Package="Module Espressif Systems"
U11: "High and Low Side Driver"
U12: "Motor Driver Power MOSFET Parallel 24-SSOP", Package="SSOP-24 Toshiba"
U13: "LED Driver IC 16 Output Linear PWM Dimming 25mA 28-TSSOP", Package="TSSOP-28 NXP Semiconductors"
USB1: library part USB, "USB 2.0, Right Angle, SMT, B Type, Receptacle, 5 Position, Black", PackageDocument=27-Jun-2003
Y1: library part SMD-CRYSTAL-8MHZ-20PF-20PPM(2P-5.0X3.2MM), "SMD Crystal 8MHz-20pF-20ppm;", Package=None

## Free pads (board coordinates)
  round 1.524 hole 1: 2(53.975,11.811) 3(51.435,11.811) 4(48.895,11.811) 5(46.355,11.811) 7(40.386,11.811) 9(37.936,11.811) 10(35.306,11.811)
  rect 1.524x1.524 hole 1: 6(43.815,11.811) 11(32.766,11.811)
  round 1.524 hole 0.762: 8(56.515,11.811)
  round 3.2 hole 3: 12(102.108,59.944) 13(102.108,27.94)
  round 1 hole 0.8: 14(1.27,40.386) 15(1.27,38.608) 16(1.27,36.957) 17(1.27,29.337)

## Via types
v1: diameter 0.6, hole 0.4, Top Layer to Bottom Layer, tented both sides, 141 vias

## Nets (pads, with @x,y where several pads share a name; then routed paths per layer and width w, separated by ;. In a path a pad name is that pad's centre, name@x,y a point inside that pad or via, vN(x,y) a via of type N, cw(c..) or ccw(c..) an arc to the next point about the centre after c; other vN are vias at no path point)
+5: C2.1 C7.1 C19.2 D2.1 D3.1 D4.1 D5.1 D6.1 D7.1 D8.1 D9.1 U1.2 U3.3 U4.3 U6.2 U11.16 USB1.1 | length 222.6
  Top Layer w0.3: USB1.1@11.187,23.13 11.965,23.13 12.065,23.23 v1(12.065,24.13) ; v1(24.22,20.727) U11.16@24.22,19.043 24.22,17.717 24.665,17.272 v1(25.781,17.272)
  Top Layer w0.4: U1.2@22.188,38.867 22.38,38.675 22.38,37.31 25.654,34.036 27.305,34.036 27.319,34.022 U4.3@30.247,34.022 30.947,34.022 32.457,32.512 33.909,32.512 ; U3.3@28.575,57.615 v1(28.575,58.674) ; v1@29.783,51.537 29.756,51.563 29.756,51.629 29.818,51.691 29.818,51.867 30.036,52.084 30.036,52.134 30.743,52.841 30.743,52.905 31.306,53.467 C19.2@31.369,53.467 ; 29.972,51.816 29.972,51.762 29.845,51.635 29.845,42.906 30.079,42.672 39.898,42.672 40.132,42.438 40.132,38.842 39.898,38.608 33.909,38.608 33.719,38.417 33.719,32.703 33.909,32.512 ; C19.2@31.229,53.886 C19.2@31.318,53.974 ; C19.2@31.242,53.873 C19.2@31.356,53.988 ; C19.2@31.483,53.988 31.572,54.076 D5.1@33.962,54.076 34.212,54.076 35.508,55.372 47.117,55.372 ; v1(31.877,17.272) 31.877,17.291 33.712,19.126 D6.1@33.962,19.126 34.212,19.126 36.168,21.082 47.244,21.082 ; C2.1@40.03,34.417 40.03,32.746 39.796,32.512 33.909,32.512 ; D8.1@47.074,19.126 47.074,20.912 47.244,21.082 ; D7.1@47.074,54.076 47.117,54.119 47.117,55.372 ; D3.1@60.074,19.126 60.074,20.958 60.198,21.082 ; D9.1@60.074,54.076 60.325,54.327 60.325,55.372 ; D2.1@73.074,19.126 72.824,19.126 70.868,21.082 60.198,21.082 ; D4.1@73.074,54.076 72.824,54.076 71.528,55.372 60.325,55.372 ; 47.117,55.372 60.325,55.372 ; 47.244,21.082 60.198,21.082
  Bottom Layer w0.3: U6.2@13.584,30.861 12.446,30.861 12.065,30.48 v1(12.065,24.13) 12.065,20.877 12.241,20.701 18.409,20.701 18.435,20.727 v1(24.22,20.727) ; v1(25.781,17.272) v1(31.877,17.272)
  Bottom Layer w0.4: v1(24.13,35.687) 25.019,34.798 29.865,34.798 30.099,34.564 30.099,25.146 25.68,20.727 v1(24.22,20.727) ; v1(28.575,58.674) 28.575,53.721 30.099,52.197
  other v1: 29.718,51.537
+5L: 1.1 2.1 3.1 4.1 5.1 6.1 7.1 8.1 C5.1 C6.1 U3.2 | length 309
  Top Layer w0.4: 7.1@29.264,63.018 29.525,62.757 29.525,56.968 ; U3.2@29.525,55.515 29.525,56.968 ; C6.1@31.394,56.896 31.323,56.968 29.525,56.968 ; 62.193,3.974 62.23,3.937 ; 87.593,3.974 87.63,3.937 ; v1(92.764,59.744) 8.1@92.764,63.018
  Top Layer w0.5: v1(92.764,59.744) 96.066,59.744 v1(96.139,59.817)
  Top Layer w0.6: 5.1@3.864,63.018 3.864,65.713 4.318,66.167 16.564,66.167 ; 1.1@11.393,7.392 11.393,4.288 11.744,3.937 24.224,3.937 ; 6.1@16.564,63.018 16.564,66.167 ; 2.1@24.093,7.392 24.093,4.068 24.224,3.937 ; 7.1@29.264,63.018 29.264,66.167 ; 3.1@36.793,7.392 36.793,4.027 36.703,3.937 ; 8.1@41.964,63.018 41.964,66.167 ; 4.1@49.493,7.392 49.493,4.027 49.403,3.937 ; 5.1@54.664,63.272 54.664,66.167 ; 62.193,3.974 1.1@62.193,7.392 ; 6.1@67.364,63.145 67.273,63.235 67.273,66.167 ; 2.1@74.893,7.392 74.893,4.027 74.803,3.937 ; 7.1@80.064,63.018 79.883,63.199 79.883,66.167 ; 87.593,3.974 3.1@87.593,7.392 ; 8.1@92.764,63.018 92.764,65.816 92.412,66.167 79.883,66.167 ; 4.1@100.293,7.392 100.293,4.662 99.568,3.937 87.63,3.937 74.803,3.937 ; 16.564,66.167 29.264,66.167 ; 24.224,3.937 36.703,3.937 ; 29.264,66.167 41.964,66.167 ; 36.703,3.937 49.403,3.937 ; 41.964,66.167 54.664,66.167 ; 49.403,3.937 62.23,3.937 74.803,3.937 ; 54.664,66.167 67.273,66.167 ; 67.273,66.167 79.883,66.167
  Bottom Layer w0.4: 1.1@11.393,7.392 11.786,7.785 C5.1@11.786,10.795
  Bottom Layer w0.5: v1(96.139,59.817) 98.679,59.817 99.695,58.801 99.695,51.435 101.346,49.784 101.346,30.734 99.314,28.702 99.314,18.034 103.378,13.97 ; 4.1@100.293,7.392 100.293,7.583 103.378,10.668 103.378,13.914
+9: C1.2 Q2.1 R5.2 U1.3 U5.2 | length 28.1
  Top Layer w0.6: v1(17.87,38.38) 18.357,38.867 U1.3@19.888,38.867 ; v1(22.823,46.381) 22.734,46.292 R5.2@22.734,44.857 C1.2@24.982,44.857
  Bottom Layer w0.6: Q2.1@13.609,34.605 13.634,34.605 13.784,34.755 13.784,34.78 14.31,35.306 16.764,35.306 ; U5.2@18.771,34.605 18.721,34.605 18.621,34.705 18.621,34.755 18.07,35.306 16.764,35.306 ; v1(22.823,46.381) 22.823,38.731 22.472,38.38 v1(17.87,38.38) 16.764,37.274 16.764,35.306
+12: IC1.3 R2.2 R11.1 R13.1 R15.2 SW1.3 U2.2 | length 55.4
  Top Layer w0.3: R15.2@16.689,57.557 16.689,58.524 16.865,58.7 20.488,58.7 20.664,58.524 20.664,54.255 21.172,53.747 R11.1@24.347,53.747 24.347,49.276 ; IC1.3@22.03,49.302 24.321,49.302 24.347,49.276 ; R13.1@26.887,46.127 25.744,46.127 24.347,47.524 24.347,49.276
  Top Layer w0.4: SW1.3@3.265,43.841 5.932,43.841 7.837,41.936 11.525,41.936 12.614,43.025 12.614,44.718 R2.2@12.625,44.73 v1(11.393,44.73) ; v1(19.775,50.572) 19.775,50.064 20.537,49.302 IC1.3@22.03,49.302
  Bottom Layer w0.4: v1(11.393,44.73) 19.203,44.73 19.775,45.302 v1(19.775,50.572)
+Vin: +.1 JDC1.1 pad.14 pad.15 pad.16 SW1.2 | length 45.3
  Top Layer w0.6: pad.16@1.27,36.957 pad.15@1.27,38.608 pad.14@1.27,40.386 1.27,44.513 3.138,46.381 SW1.2@3.265,46.381 6.343,46.381 6.694,46.732 6.694,50.953 5.043,52.604 5.043,57.206 5.394,57.557 12.386,57.557 12.737,57.206 JDC1.1@12.737,54.763
  Bottom Layer w0.6: SW1.2@3.265,46.381 3.392,46.381 6.35,43.423 6.35,40.259 +.1@4.699,38.608
+VM: C17.1 Cx10.2 Q3.1 U5.3 U6.3 U12.13 U12.14 U12.24 | length 122.2
  Top Layer w0.4: v1(62.293,31.051) 64.96,31.051 65.532,30.48 v1(65.532,27.813) ; v1(76.835,36.322) 76.835,40.259 v1(77.47,40.894) ; v1(81.153,43.434) 81.097,43.378 81.097,42.601 ; U12.14@81.747,38.819 U12.13@81.097,38.819 81.097,42.601 ; U12.24@88.247,38.819 88.247,42.366 88.481,42.601 ; 92.176,42.601 88.481,42.601 ; 81.097,42.601 88.481,42.601
  Top Layer w0.5: v1(28.306,31.75) 45.339,31.75 v1(45.403,31.686) ; Cx10.2@92.176,41.386 92.176,42.601 92.176,43.815 C17.1@92.329,43.967
  Bottom Layer w0.3: U5.3@20.871,33.655 28.145,33.655 28.321,33.479 28.321,31.765 v1(28.306,31.75)
  Bottom Layer w0.4: U6.3@15.684,29.911 15.734,29.911 18.086,27.559 19.705,27.559 19.939,27.793 19.939,30.856 ; Q3.1@18.796,30.856 20.061,30.856 20.828,31.623 20.828,33.455 20.871,33.498 U5.3@20.871,33.655 ; v1(45.403,31.686) 46.039,31.05 62.292,31.05 v1(62.293,31.051) ; v1(65.532,27.813) 65.532,24.618 65.766,24.384 76.07,24.384 77.089,25.403 77.089,35.687 76.835,35.941 v1(76.835,36.322) ; v1(77.47,40.894) 77.47,42.545 78.359,43.434 v1(81.153,43.434)
ADC_POWER: Cx6.2 IC1.6 IC1.7 U10.4 | length 44.2
  Top Layer w0.2: U10.4@61.992,42.816 v1(61.992,44.577)
  Top Layer w0.3: IC1.6@27.68,49.302 IC1.7@27.68,50.572 28.803,50.572 v1(28.88,50.496) ; v1(33.782,46.736) v1(41.91,46.736) ; v1(56.261,48.514) v1(60.198,48.514)
  Bottom Layer w0.2: v1(61.992,44.577) 61.992,45.444 Cx6.2@62.103,45.555
  Bottom Layer w0.3: v1(28.88,50.496) 29.387,50.496 33.147,46.736 v1(33.782,46.736) ; v1(41.91,46.736) 53.594,46.736 55.372,48.514 v1(56.261,48.514) ; v1(60.198,48.514) 60.198,45.339 60.96,44.577 v1(61.992,44.577)
AO1: Cx11.1 J3.1 U12.1 U12.2 | length 29.9
  Top Layer w0.3: v1(87.741,47.736) 87.597,47.592 U12.2@87.597,46.069 U12.1@88.247,46.069
  Bottom Layer w0.5: v1(87.741,47.736) 88.689,48.684 94.511,48.684 94.804,48.391 94.804,33.975 96.878,31.901 J3.1@97.282,31.497 97.29,31.505 99.307,31.505 Cx11.1@99.314,31.512
AO2: Cx11.2 J3.2 U12.5 U12.6 | length 31.8
  Top Layer w0.3: U12.5@85.647,46.069 U12.6@84.997,46.069 84.997,47.231 85.526,47.76 86.368,47.76 v1(86.995,48.387)
  Bottom Layer w0.5: v1(86.995,48.387) 87.992,49.384 95.338,49.384 95.631,49.091 95.631,35.154 J3.2@97.282,33.503 97.287,33.508 99.31,33.508 Cx11.2@99.314,33.512
BO1: Cx12.1 J4.1 U12.11 U12.12 | length 25.4
  Top Layer w0.3: U12.12@81.097,46.069 U12.11@81.747,46.069 81.747,48.473 82.89,49.616 v1(85.766,49.616)
  Top Layer w0.5: v1(95.529,51.034) 95.529,51.023 95.527,51.021 95.527,48.11 J4.1@97.282,46.355
  Bottom Layer w0.5: v1(85.766,49.616) 87.171,51.021 95.516,51.021 v1(95.529,51.034) ; J4.1@97.282,46.355 97.337,46.3 99.259,46.3 Cx12.1@99.314,46.244
BO2: Cx12.2 J4.2 U12.7 U12.8 | length 19.5
  Top Layer w0.3: U12.7@84.347,46.069 U12.8@83.697,46.069 83.697,47.166 84.791,48.26 85.598,48.26 v1(86.36,49.022)
  Bottom Layer w0.5: v1(86.36,49.022) 87.63,50.292 95.42,50.292 97.282,48.43 J4.2@97.282,48.361 97.34,48.303 99.256,48.303 Cx12.2@99.314,48.244
BT_Config: Cx7.2 R24.1 SW2.2 SW2.3 U10.23 | length 19.4
  Top Layer w0.3: Cx7.2@32.258,27.686 32.308,27.686 33.042,28.42 33.752,28.42 SW2.3@34.252,28.92 SW2.2@42.202,28.92 42.327,28.92 43.592,27.655 44.354,27.655 R24.1@44.704,27.305 46.101,27.305 46.482,27.686 46.482,29.591 46.762,29.871 U10.23@48.292,29.871
BT_IN: Cx8.2 R25.1 SW3.2 SW3.3 U10.14 | length 22.4
  Top Layer w0.3: Cx8.2@32.004,47.155 32.954,47.155 33.627,47.828 33.627,47.942 34.127,48.442 SW3.3@34.252,48.442 SW3.2@42.202,48.442 43.689,48.442 44.506,47.625 R25.1@44.704,47.625 48.133,47.625 49.292,46.466 U10.14@49.292,42.816
C_LED_WS2812: R37.1 U10.8 | length 23.2
  Top Layer w0.2: R37.1@41.656,51.816 41.854,51.816 42.454,51.216 44.231,51.216 v1(44.323,51.308) ; U10.8@56.912,42.816 57.023,42.927 v1(57.023,44.704)
  Bottom Layer w0.2: v1(44.323,51.308) 55.372,51.308 57.023,49.657 v1(57.023,44.704)
D+: U11.5 USB1.3 | length 10.1
  Top Layer w0.2: USB1.3@11.187,21.53 11.23,21.573 14.144,21.573 v1(14.187,21.616) ; v1(19.14,22.759) U11.5@19.14,24.443
  Bottom Layer w0.2: v1(14.187,21.616) 17.997,21.616 v1(19.14,22.759)
D-: U11.6 USB1.2 | length 8.5
  Top Layer w0.2: USB1.2@11.187,22.33 11.211,22.354 13.528,22.354 v1(13.552,22.378) ; v1(17.87,22.886) U11.6@17.87,24.443
  Bottom Layer w0.2: v1(13.552,22.378) 17.362,22.378 v1(17.87,22.886)
DIR_MA1: U12.22 U13.9 | length 6.8
  Top Layer w0.3: U13.9@83.834,33.427 83.834,34.686 85.092,35.944 85.246,35.944 86.947,37.645 U12.22@86.947,38.819
DIR_MA2: U12.21 U13.10 | length 6.8
  Top Layer w0.3: U13.10@83.173,33.427 83.173,34.732 84.885,36.444 85.039,36.444 86.297,37.702 U12.21@86.297,38.819
DIR_MB1: U12.17 U13.11 | length 5.9
  Top Layer w0.3: U13.11@82.513,33.427 82.513,35.408 83.678,36.573 83.678,37.48 83.697,37.499 U12.17@83.697,38.819
DIR_MB2: U12.16 U13.12 | length 5.9
  Top Layer w0.3: U13.12@81.878,33.427 81.878,35.48 83.047,36.649 U12.16@83.047,38.819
